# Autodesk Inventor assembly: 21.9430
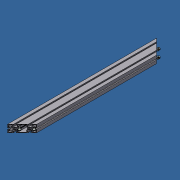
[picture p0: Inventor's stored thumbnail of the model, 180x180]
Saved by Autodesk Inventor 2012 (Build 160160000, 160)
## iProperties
Created: 2013-10
Part Number: 21.9430
Document SubType Name: Assembly
Designer: Admin
Description: STRENGTHENING ELE 45X90H
Author: Admin
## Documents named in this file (4)
- C:\Andys Backup Data\ANDY'S INVENTOR\INVENTOR LIBRARIES\PARTS LIBRARY\FEET WHEELS FLOOR FASTENING SUPPORTS\21.9430 STRENGTHENING ELE 45X90H.iam
- C:\Andys Backup Data\ANDY'S INVENTOR\INVENTOR LIBRARIES\PARTS LIBRARY\FASTENING ELEMENTS\SCREWS CAP\21.1208 M8X35.ipt
- C:\Andys Backup Data\ANDY'S INVENTOR\INVENTOR LIBRARIES\PARTS LIBRARY\FASTENING ELEMENTS\NUTS\21.1351_2 M8 SQUARE NUT POS FXG.ipt
- C:\Andys Backup Data\ANDY'S INVENTOR\INVENTOR LIBRARIES\PARTS LIBRARY\FEET WHEELS FLOOR FASTENING SUPPORTS\SUBCOMPONENTS\21.9430_1_45X90_PROFILE.ipt
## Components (9 placed, 3 different names)
1. 21.9430/1_SE 45X90H PROFILE:1 — Insert:1, Insert:2, Insert:3, Insert:4, Mate:5, Angle:1, Mate:6, Mate:7, Mate:8, Angle:3, Angle:4
2. 21.1208  M8 x 35:1 — Insert:1, Mate:2
3. 21.1208  M8 x 35:2 — Insert:2, Mate:1
4. 21.1208  M8 x 35:3 — Insert:4, Mate:3
5. 21.1208  M8 x 35:4 — Insert:3, Mate:4
6. 21.1351_2 M8 SQUARE NUT POS FXG:1 — Mate:1, Mate:7, Angle:3
7. 21.1351_2 M8 SQUARE NUT POS FXG:2 — Mate:2, Mate:8, Angle:4
8. 21.1351_2 M8 SQUARE NUT POS FXG:3 — Mate:3, Angle:2, Mate:6
9. 21.1351_2 M8 SQUARE NUT POS FXG:4 — Mate:4, Mate:5, Angle:1, Angle:2
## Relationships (16: Mate 8, Insert 4, Angle 4)
- Insert:1: 21.9430/1_SE 45X90H PROFILE:1 ↔ 21.1208  M8 x 35:1
- Insert:2: 21.9430/1_SE 45X90H PROFILE:1 ↔ 21.1208  M8 x 35:2
- Insert:3: 21.9430/1_SE 45X90H PROFILE:1 ↔ 21.1208  M8 x 35:4
- Insert:4: 21.9430/1_SE 45X90H PROFILE:1 ↔ 21.1208  M8 x 35:3
- Mate:1: 21.1208  M8 x 35:2 ↔ 21.1351_2 M8 SQUARE NUT POS FXG:1
- Mate:2: 21.1208  M8 x 35:1 ↔ 21.1351_2 M8 SQUARE NUT POS FXG:2
- Mate:3: 21.1208  M8 x 35:3 ↔ 21.1351_2 M8 SQUARE NUT POS FXG:3
- Mate:4: 21.1208  M8 x 35:4 ↔ 21.1351_2 M8 SQUARE NUT POS FXG:4
- Mate:5: 21.9430/1_SE 45X90H PROFILE:1 ↔ 21.1351_2 M8 SQUARE NUT POS FXG:4
- Angle:1: 21.9430/1_SE 45X90H PROFILE:1 ↔ 21.1351_2 M8 SQUARE NUT POS FXG:4
- Angle:2: 21.1351_2 M8 SQUARE NUT POS FXG:3 ↔ 21.1351_2 M8 SQUARE NUT POS FXG:4
- Mate:6: 21.9430/1_SE 45X90H PROFILE:1 ↔ 21.1351_2 M8 SQUARE NUT POS FXG:3
- Mate:7: 21.9430/1_SE 45X90H PROFILE:1 ↔ 21.1351_2 M8 SQUARE NUT POS FXG:1
- Mate:8: 21.9430/1_SE 45X90H PROFILE:1 ↔ 21.1351_2 M8 SQUARE NUT POS FXG:2
- Angle:3: 21.9430/1_SE 45X90H PROFILE:1 ↔ 21.1351_2 M8 SQUARE NUT POS FXG:1
- Angle:4: 21.9430/1_SE 45X90H PROFILE:1 ↔ 21.1351_2 M8 SQUARE NUT POS FXG:2
